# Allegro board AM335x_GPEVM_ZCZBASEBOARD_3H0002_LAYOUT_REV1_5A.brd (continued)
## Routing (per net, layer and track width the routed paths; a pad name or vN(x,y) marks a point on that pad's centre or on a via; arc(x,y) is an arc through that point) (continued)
N17345501: length 2.7
  TOP w0.121: v1(153.96,91.73) SW4.1
  BOTTOM w0.121: R122.2 v1(153.96,91.73)
N17345515: length 2.7
  TOP w0.121: v1(153.96,89.19) SW4.2
  BOTTOM w0.121: R123.2 v1(153.96,89.19)
N17345519: length 2.7
  TOP w0.121: v1(153.96,86.65) SW4.3
  BOTTOM w0.121: R124.2 v1(153.96,86.65)
N17345529: length 2.7
  TOP w0.121: v1(153.96,84.11) SW4.4
  BOTTOM w0.121: R125.2 v1(153.96,84.11)
N17345551: length 2.7
  TOP w0.121: v1(153.96,81.57) 155.61,81.57
  BOTTOM w0.121: R126.2 v1(153.96,81.57)
N17345553: length 2.7
  TOP w0.121: v1(153.96,79.03) SW4.6
  BOTTOM w0.121: R127.2 v1(153.96,79.03)
N17345567: length 2.7
  TOP w0.121: v1(153.96,76.49) SW4.7
  BOTTOM w0.121: R128.2 v1(153.96,76.49)
N17345577: length 2.7
  TOP w0.121: v1(153.96,73.95) SW4.8
  BOTTOM w0.121: R129.2 v1(153.96,73.95)
N17563948: length 133.9
  TOP w0.121: R84.1 76.72,104.66 v1(76.72,104.94) ; Q1.G 35.71,162.1 R86.2 38.06,162.09 42.91,157.24 57.24,157.24 58.05,156.42 58.05,154.85 58.53,154.37 59.9,154.37 60.46,154.93 67.93,154.93 68.67,154.19 v1(74.41,154.19) 74.81,154.59 81.56,154.59 81.82,154.33 84.55,154.33 84.79,154.09 85.21,154.09 86.02,154.9 R85.1 86.27,155.61 v1(86.78,156.12) ; v1(98.46,155.61) 98.59,155.74 R509.1
  BOTTOM w0.121: v1(98.46,155.61) 98.84,155.99 98.84,160.25 97.96,161.13 89.31,161.13 88.87,160.69 88.87,158.22 v1(86.78,156.12) ; v1(76.72,104.94) 76.72,105.93 77.53,106.74 v1(77.53,116.5) 77.53,117.44 77.14,117.82 77.14,119.18 73.74,122.58 73.74,128.68 74.97,129.91 74.97,135.61 74.67,135.91 74.67,140.39 73.95,141.11 73.95,148.5 74.08,148.63 74.08,150.79 73.95,150.91 73.95,153.73 v1(74.41,154.19)
N17563994: length 1.9
  TOP w0.121: D4.2 35.6,167.06 v1(35.6,168.03)
  BOTTOM w0.121: R80.1 v1(35.6,168.03)
N17563997: length 2.7
  TOP w0.121: Q1.D 33.33,164.88 D4.1
N17564510: length 2.8
  TOP w0.121: D5.1 29.26,166.79 Q2.D
N17564514: length 2
  TOP w0.121: D5.2 v1(31.26,168.06)
  BOTTOM w0.121: v1(31.26,168.06) 31.26,167.97 31.28,167.96 R81.1
N17564644: length 2.8
  TOP w0.121: D6.1 24.81,166.79 Q3.D
N17564648: length 2
  TOP w0.121: v1(26.83,168.06) 26.83,167.06 D6.2
  BOTTOM w0.121: R82.1 v1(26.83,168.06)
N17564780: length 2.7
  TOP w0.121: D7.1 20.37,166.92 Q4.D
N17564784: length 2
  TOP w0.121: D7.2 v1(22.5,168.06)
  BOTTOM w0.121: R83.1 22.52,167.96 22.5,167.97 v1(22.5,168.06)
N17564892: length 216.9
  TOP w0.121: 93.26,155.74 v1(92.49,155.74) 92.49,157.96 91.48,158.98 91.48,162.72 90.78,163.42 81.83,163.42 81.19,162.79 81.19,162.09 80.3,161.2 78.27,161.2 75.73,158.66 70.4,158.66 67.98,156.25 v1(58.58,156.25) ; R87.1 77.2,100.54 77.2,102.08 77.24,102.11 77.24,102.48 77.2,102.52 v1(77.2,102.91) 77.2,103.26 77.15,103.31 77.15,104.54 77.53,104.91 77.53,105.09 R88.1 ; v1(32.3,163.11) 32.3,162.22 32.04,161.96 R93.2 31.27,161.97 Q2.G ; v1(22.64,156.69) v1(53.38,156.69)
  LY3 w0.133: v1(22.64,156.69) 23.77,155.56 28.13,155.56 32.3,159.73 v1(32.3,163.11) ; v1(22.18,103.38) 23.1,104.3 52.36,104.3 53.28,103.39 66.18,103.39 67.42,104.62 68.17,104.62 69.89,102.91 72.93,102.91 73.26,102.59 74.52,102.59 74.84,102.91 v1(77.2,102.91)
  BOTTOM w0.121: v1(58.58,156.25) 58.14,156.69 v1(53.38,156.69) ; v1(22.64,156.69) 22.64,148.2 23.21,147.63 23.21,117.41 23.36,117.26 23.36,114.97 23.21,114.82 23.21,112.34 21.45,110.57 21.45,104.73 22.18,104 v1(22.18,103.38)
N17564904: length 188.3
  TOP w0.121: v1(24.04,156.12) v1(54.14,156.12) ; R511.1 87.16,153.83 85.65,153.83 85.41,153.6 84.59,153.6 84.47,153.71 68.03,153.71 67.15,154.59 66.55,154.59 65.98,154.01 58.54,154.01 57.31,155.24 v1(57.31,156.12) ; v1(27.98,162.47) 27.47,161.96 R95.2 26.83,163.42 Q3.G ; v1(23.66,102.94) 35.24,102.94 35.26,102.97 35.63,102.97 35.65,102.94 41.28,102.94 42.76,104.42 50.96,104.42 52.16,105.62 65.14,105.62 66.12,104.65 66.68,104.65 66.94,104.91 68.21,104.91 69.26,103.86 70.07,103.86 R90.1 R89.1
  LY3 w0.133: v1(24.04,156.12) 25.54,156.12 26.83,157.42 26.83,158.36 27.98,159.5 v1(27.98,162.47)
  BOTTOM w0.121: v1(57.31,156.12) v1(54.14,156.12) ; v1(23.66,102.94) 23.66,104.05 21.69,106.02 21.69,110.46 23.46,112.23 23.46,114.64 23.61,114.79 23.61,120 23.46,120.15 23.46,148.24 23.13,148.58 23.13,155.21 v1(24.04,156.12)
N17564916: length 157.6
  TOP w0.121: v1(23.25,161.96) R94.2 22.38,161.97 Q4.G ; R91.1 73.51,97.64 73.51,98.53 72.8,99.23 72.47,99.23 72.47,99.23 71.88,99.23 71.87,99.23 71.46,99.23 71.45,99.23 71.28,99.23 71.06,99.44 71.06,102.31 69.76,103.62 69.16,103.62 68.11,104.67 67.04,104.67 66.78,104.4 66.01,104.4 65.04,105.38 52.4,105.38 52.22,105.19 52.21,105.19 51.19,104.18 42.86,104.18 41.19,102.5 35.93,102.5 35.9,102.53 v1(35.44,102.53) ; v1(59.6,133.01) 58.84,133.77 57.44,133.77 56.17,135.04 55.28,135.04 54.52,135.8 47.28,135.8 v1(46.52,136.56) ; R92.1 44.6,115.61 43.78,114.79 43.53,114.79 42.75,114.01 40.82,114.01 40.14,113.34 39.45,113.34 39.19,113.6 39.19,113.63 39.15,113.67 v1(39.15,115.35) 37.5,115.35 36.64,114.49 v1(36.64,113.07)
  BOTTOM w0.121: v1(35.44,102.53) 35.44,111.87 v1(36.64,113.07) ; R512.1 v1(59.6,133.01) ; v1(39.15,115.35) 39.15,116.01 44.61,121.47 44.61,131.74 46.52,133.64 v1(46.52,136.56) 46.52,140.3 45.55,141.26 45.55,144 41.97,147.59 41.97,158.18 37.3,162.85 33.31,162.85 32.47,162.01 23.74,162.01 23.69,161.96 v1(23.25,161.96)
N17601395: length 84.6
  TOP w0.121: v1(17.87,109.54) 17.31,108.98 R492.2 ; R349.2 65.19,95.03 v1(64.91,95.31) ; U14.7 v1(21.85,126.38)
  LY3 w0.133: v1(17.87,109.54) 16.72,108.39 16.72,104.4 19.29,101.84 23.56,101.84 24.24,102.52 24.41,102.52 25.31,103.42 38.15,103.42 42.58,98.99 46.66,98.99 50.33,95.31 v1(64.91,95.31)
  BOTTOM w0.121: v1(17.87,109.54) 17.87,109.56 19.21,110.91 20.61,110.91 21.78,112.08 21.78,115.3 22.39,115.91 22.39,124.75 21.85,125.29 v1(21.85,126.38)
N17618848: length 9.8
  TOP w0.121: U25.6 29.48,55.36 29.42,55.41 26.96,55.41 26.3,56.07 26.3,56.85 24.92,58.22 Y3.1 22.12,58.22 C212.2
N17618850: length 8.9
  TOP w0.121: C204.2 22.79,53.76 23.15,54.12 Y3.2 24.92,54.12 26.09,55.28 26.74,55.28 26.86,55.16 29.29,55.16 29.5,54.96 U25.7
N17618867: length 6.7
  TOP w0.121: U25.45 32.18,58.82 32.1,58.91 32.1,59.63 32.31,59.84 32.31,63.55 TP47.1
N17619022: length 8.5
  TOP w0.121: U25.42 33.38,60.21 32.81,60.79 32.81,63.04 33.13,63.36 34.15,63.36 34.45,63.66 34.71,63.66 35.09,64.05 35.34,64.05 TP49.1
N17619024: length 7.5
  TOP w0.121: TP48.1 33.67,63.64 33.06,63.64 32.56,63.14 32.56,60.69 32.98,60.26 32.98,59.33 33.03,59.28 33.03,58.92 32.98,58.88 U25.43
N17619221: length 4.8
  TOP w0.121: U25.40 34.18,59.71 v1(34.58,60.11) R405.1 R479.1
  BOTTOM w0.121: v1(34.58,60.11) R405.1
N17619435: length 1.1
  BOTTOM w0.121: R395.2 TP50.1
N17619707: length 3
  TOP w0.121: U25.41 33.78,60.52 R394.2
N17619739: length 6.4
  TOP w0.121: U25.46 31.78,59.7 32.06,59.98 32.06,64.28 TP46.1
N17684279: length 4.4
  TOP w0.121: R239.1 v1(129.45,79.79)
  BOTTOM w0.102: 130.72,79.54 132.12,79.54 J8.12
  BOTTOM w0.121: 130.72,79.54 129.7,79.54 v1(129.45,79.79)
N17684406: length 119.6
  TOP w0.121: U4.33 88.45,37.36 88.36,37.44 v1(88.36,37.53) ; v1(13.12,17.06) R629.1 13.09,16.13 SW6.3 SW6.4
  LY3 w0.133: v1(56.93,34.33) 54.65,34.33 54.58,34.39 27.92,34.39 22.9,29.37 22.9,24.29 21.88,23.28 16.29,23.28 15.02,22.01 15.02,18.33 13.88,17.18 13.25,17.18 v1(13.12,17.06)
  LY4 w0.133: v1(88.36,37.53) 87.91,37.53 87.29,38.16 84.77,38.16 84.69,38.08 84.55,38.08 83.6,37.13 83.6,36.36 83.22,35.98 83.22,25.18 82.33,24.29 79.16,24.29 76.24,27.22 63.03,27.22 60.94,29.31 60.68,29.31 60.42,29.57 60.42,29.82 57.44,32.8 57.44,33.82 v1(56.93,34.33)
  BOTTOM w0.203: R63.1 87.79,39.2 87.62,39.03 87.62,37.98 88.07,37.53 v1(88.36,37.53)
N17710761: length 4.8
  TOP w0.102: v2(84.2,79.4) U2.J3
  BOTTOM w0.121: R22.2 83.1,76.82 83.49,77.21 83.52,77.21 83.77,77.46 83.77,78.27 83.95,78.45 83.95,78.89 84.2,79.14 v2(84.2,79.4)
N18082443: length 93.4
  TOP w0.121: U13.4 v1(28.18,118.08) ; R328.2 81.91,154.6 81.66,154.84 70.05,154.84 69.63,155.26 59.15,155.26 v1(58.74,154.84) ; v1(55.62,154.84) v1(32.84,154.84)
  BOTTOM w0.121: v1(58.74,154.84) v1(55.62,154.84) ; v1(28.18,118.08) 28.15,118.1 28.15,134.25 32.17,138.26 32.17,154.16 v1(32.84,154.84)
N18136628: length 17.2
  TOP w0.121: U7.7 139.67,71.98 v1(139.74,72.05)
  BOTTOM w0.121: TP54.1 137.2,61.89 137.2,70.14 139.1,72.05 v1(139.74,72.05) 139.74,70.9
N18365790: length 3
  TOP w0.203: v1(84.78,35.34) 85.02,35.1 85.71,35.1 85.72,35.09 U4.39
  BOTTOM w0.381: R57.1 84.65,35.47 v1(84.78,35.34)
N18368859: length 1.9
  TOP w0.203: U6.7 93.26,23.78 R69.2
N19410176: length 3.5
  TOP w0.121: U15.6 27.76,138.43 v1(28.1,138.09)
  BOTTOM w0.121: R518.1 28.36,138.34 v1(28.1,138.09)
N19410226: length 2.4
  TOP w0.121: U13.12 v1(19.02,118.73)
  BOTTOM w0.121: R519.1 18.4,118.73 v1(19.02,118.73)
N19440113: length 0.4
  TOP w0.121: U24.B2 U24.B1
N19440133: length 0.4
  TOP w0.121: U24.D2 U24.D1
N19440219: length 2.9
  TOP w0.121: U24.A3 U24.B3 U24.C4 U24.D4 155.59,144.71 C264.1
N19490589: length 9.9
  TOP w0.102: 77.1,80.08 77.2,80.08 77.21,80.07 77.93,80.07 U2.A3
  TOP w0.121: TP24.1 69.9,78.66 70.78,78.66 71.16,79.03 71.51,79.03 71.89,79.42 75.74,79.42 76.39,80.08 77.1,80.08
N19558182: length 2.1
  TOP w0.121: U32.2 59.97,35.65 R544.1
N19577113: length 3.4
  TOP w0.121: U4.26 91.25,37.21 91.41,37.38 v1(92.49,37.38)
  BOTTOM w0.121: 91.86,36.11 92.11,36.36 92.11,36.99 v1(92.49,37.38)
N19577116: length 4.7
  TOP w0.121: v1(93.38,34.45) 92.82,33.89 U4.19
  BOTTOM w0.121: v1(93.38,34.45) 92.64,35.2 92.64,36.63 93,36.99 R60.1
N21001557: length 9.1
  TOP w0.121: SW5.2 6.8,45.52 7.07,45.25 v1(7.94,45.25) 7.94,44.54 6.8,43.4 SW5.1
  BOTTOM w0.121: v1(7.94,45.25) R156.2 R112.2
N21001559: length 8
  TOP w0.635: SW5.3 10.8,43.25 v1(10.83,43.34) ; SW5.4 v1(10.8,45.45)
  BOTTOM w0.121: v1(10.83,43.34) 10.8,43.38 v1(10.8,45.45) 10.83,45.48 R559.1 R560.2
N21339295: length 1.8
  TOP w0.121: Q5.D 128.6,160.95 129.39,161.73 R23.2
N21519462: length 2.4
  TOP w0.121: v1(92.18,57.44) U33.H8
  BOTTOM w0.076: 92.7,56.36 92.59,56.47 92.59,57.03 v1(92.18,57.44)
  BOTTOM w0.121: R572.2 92.75,56.32 92.7,56.36
N21521030: length 2.4
  TOP w0.121: v1(77.58,57.44) U34.H8
  BOTTOM w0.121: R573.2 78.14,56.32 77.99,56.47 77.99,57.03 v1(77.58,57.44)
N21540235: length 3.7
  TOP w0.121: v1(11.98,74.81) 11.01,74.81 10.31,75.52 U58.14
  BOTTOM w0.121: R585.1 v1(11.98,74.81)
N21540301: length 2.2
  TOP w0.121: D11.1 15.04,87.18 R586.2
N21540351: length 3.4
  TOP w0.121: U61.4 13.75,88.55 13.63,88.43 R588.1 12.48,87.92
N21540405: length 3
  TOP w0.121: U58.60 13.27,85.17 13.5,85.39 13.5,86.14 13.63,86.27 R586.1
N21540429: length 3.2
  TOP w0.121: U58.36 23.18,76.02 23.22,75.98 TP52.1
N21815253: length 1.9
  TOP w0.121: 21.5,97.07 20.81,97.07 20.46,96.71 U54.4
N21825062: length 4.5
  TOP w0.121: U58.59 v1(13.77,82.61)
  BOTTOM w0.121: R627.2 R591.1 14.09,83.4 14.09,82.92 v1(13.77,82.61) 14.01,82.37 R590.2
N21837772: length 3.7
  TOP w0.121: R592.2 18.58,69.5 18.77,69.7 U58.32
N21889047: length 3.7
  TOP w0.121: R593.2 16.55,69.5 16.77,69.73 U58.28
N22489222: length 4.1
  TOP w0.121: v1(105.16,57.81) 107.79,57.81 R594.1
  BOTTOM w0.121: U62.9 v1(105.16,57.81)
N22502363: length 3.4
  BOTTOM w0.381: C337.1 R603.1 103.03,51.83 103.66,52.45 U62.5
N22504661: length 4.9
  BOTTOM w0.121: R597.1 C341.1 R596.2 107.34,52.42 107.3,52.39 106.36,53.33 U62.1
N22518686: length 2
  TOP w0.121: R625.1 R624.1 C352.1
N22552028: length 4.2
  TOP w0.121: U63.1 67.28,100.05 68.21,100.98 69.53,100.98 R9.1
N22597176: length 3
  TOP w0.121: U4.38 85.69,35.49 85.25,35.93 TP53.1
N23180701: length 2.2
  TOP w0.121: C7.1 61.98,102.62 62.91,102.62 63.58,101.95 U63.4

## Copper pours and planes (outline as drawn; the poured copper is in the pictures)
DGND on TOP: 155.36,146.34 154.6,146.34 154.09,145.83 154.09,143.8 153.96,143.67 153.07,143.67 152.95,143.8 152.95,144.56 152.44,144.56 151.42,145.58 147.48,145.58 147.36,145.45 147.36,142.91 147.74,142.53 156.37,142.53 156.5,142.66 156.5,146.34 156.37,146.34 156.25,146.21 156.25,145.83 155.99,145.58 155.99,144.06 155.1,144.06 155.1,145.83 155.36,146.09
DGND on LY2_GND: 1.27,1.28 39.49,1.28 39.64,1.43 39.64,2.01 39.83,2.21 40.86,2.21 41.03,2.04 41.03,1.49 41.25,1.27 168.73,1.27 168.73,168.73 1.27,168.73
DGND on LY5_GND: 1.27,1.27 168.73,1.27 168.73,168.73 1.27,168.73
V1_2D on TOP: 149.26,15.53 155.99,15.53 156.37,15.91 156.37,18.96 156.12,19.21 151.93,19.21 151.8,19.09 151.8,17.06 151.55,16.8 149.9,16.8 149.77,16.93 149.01,16.93 149.01,15.79
V1_8D on LY4: 134.78,125.64 137.96,125.64 137.96,116.62 134.28,116.62 134.28,50.08 132.24,50.08 132.24,88.3 129.83,88.3 129.83,122.34 134.53,122.34 134.53,125.39
V3_3D on TOP: 113.96,24.93 112.05,24.93 111.92,24.8 111.92,23.91 111.67,23.66 110.65,23.66 110.65,22.64 110.78,22.52 113.83,22.52 113.96,22.64
V3_3D on BOTTOM: 111.42,22.01 113.58,22.01 113.96,22.39 113.96,24.68 113.7,24.93 111.29,24.93 111.16,24.8 111.16,22.26
V3_3D on LY4: 47.28,139.1 47.28,139.23 36.87,139.23 36.87,115.1 10.07,115.1 10.07,95.16 28.36,95.16 28.36,66.59 39.53,66.59 39.53,50.58 28.74,50.58 28.74,56.93 27.09,56.93 27.09,51.35 12.1,51.35 12.1,47.79 7.3,47.79 7.3,57.01 1.43,57.01 1.43,1.31 114.72,1.31 114.72,25.82 102.27,25.82 102.27,7.66 51.22,7.66 51.22,72.33 32.93,72.33 32.93,99.35 13.63,99.35 13.63,104.3 68.24,104.3 68.24,120.31 75.6,120.31 75.6,146.85 64.43,146.85 64.43,139.1
V3_3FTDI on LY3: 1.27,71.77 1.27,80.43 8.55,80.43 8.55,98.11 20.64,98.11 20.64,71.77
V5_0D on TOP: 155.1,147.87 155.36,147.61 155.36,146.98 153.33,146.98 152.82,146.47 152.82,144.94 152.69,144.82 152.44,144.82 151.42,145.83 147.36,145.83 146.85,146.34 146.85,147.99 147.48,148.63 152.06,148.63 152.82,147.87
V5_0D on LY4: 152.95,148.63 152.95,70.01 140.37,70.01 140.37,70.14 137.96,70.14 137.96,45.25 129.32,45.25 129.32,25.56 126.53,25.56 126.53,49.57 134.66,49.57 134.66,116.37 138.21,116.37 138.21,125.89 134.53,125.89 134.15,125.51 134.15,122.97 129.7,122.97 129.7,130.34 148.5,130.34 148.5,148.63
VBAT on TOP: 159.8,146.47 159.8,149.39 159.55,149.64 158.15,149.64 157.39,148.88 157.39,148.25 156.63,147.48 156.63,146.85 157.14,146.85 157.52,146.47
VBAT on TOP: 11.21,150.91 15.02,150.91 15.15,151.04 15.15,151.68 14.9,151.93 11.21,151.93
VBAT on TOP: 83.35,10.58 93.38,10.58 93.89,11.09 93.89,14.01 91.48,16.42 91.48,18.71 91.22,18.96 91.22,21.88 87.79,21.88 87.54,21.63 86.65,21.63 86.65,21.75 86.52,21.75 86.52,22.26 82.97,22.26 82.97,18.96 86.14,18.96 86.27,18.83 86.27,14.9 85.89,14.52 78.4,14.52 78.33,14.45 77.82,14.45 77,13.63 77,8.8 77.25,8.55 78.9,8.55 79.67,9.31 79.67,11.21 80.05,11.59 82.33,11.59
VBAT on LY4: 106.21,163.74 106.21,157.9 120.43,157.9 120.43,42.46 98.34,42.46 98.34,37.88 83.86,37.88 83.86,22.9 56.68,22.9 56.68,84.11 50.71,84.11 50.71,103.8 14.01,103.8 14.01,99.61 33.44,99.61 33.44,72.63 51.6,72.63 51.6,8.04 101.89,8.04 101.89,26.33 115.1,26.33 115.1,1.28 138.44,1.28 138.44,2.96 139.1,3.62 140.63,3.62 140.63,8.93 142.28,10.58 142.28,24.04 141.39,24.93 126.4,24.93 126.4,50.08 131.86,50.08 131.86,87.29 128.82,87.29 128.82,148.88 153.33,148.88 153.33,145.96 159.3,145.96 159.3,154.47 134.53,154.47 134.53,163.74
VBUS1_OTG_CAP on TOP: 153.38,161.15 153.38,156.91 154.09,156.2 159.6,156.2 159.9,156.5 159.9,160.13 158.66,161.38 153.61,161.38
VDD1_SMPS on TOP: 79.54,43.29 80.81,43.29 81.32,43.8 81.32,46.28 79.16,46.28 79.16,43.67
VDD1_SMPS on TOP: 72.3,37.68 74.99,37.68 75.25,37.43 75.25,36.21 75.02,35.98 72.45,35.98 72.27,36.16 72.27,37.65
VDD1_SMPS on LY3: 125.2,51.22 125.2,45.5 121.7,45.5 121.7,44.11 76.11,44.11 76.11,34.07 66.71,34.07 66.71,47.28 117.39,47.28 117.39,51.22
VDD2_SMPS on TOP: 76.24,36.49 77.76,36.49 78.27,36.99 78.27,38.65 78.14,38.77 76.24,38.77 76.11,38.65 76.11,36.61
VDD2_SMPS on TOP: 68.74,49.06 69.51,49.06 69.89,48.68 70.52,48.68 70.78,48.42 70.78,47.28 70.27,46.77 69.89,46.77 69.76,46.9 69.76,47.79 69.63,47.92 68.74,47.92
VDD2_SMPS on LY4: 78.14,39.03 75.98,39.03 75.98,32.63 72.43,32.63 72.43,48.93 69.25,48.93 69.25,29.48 78.14,29.48
VDD3_SMPS on TOP: 90.97,44.74 93.13,44.74 93.26,44.87 93.26,46.52 92.87,46.9 91.1,46.9 90.84,46.65 90.84,44.87
VDD_CORE on TOP: 72.55,46.77 72.55,45.76 72.81,45.5 75.09,45.5 75.6,46.01 75.6,46.9 75.22,47.28 73.06,47.28
VDD_CORE on BOTTOM: 73.06,47.28 72.55,46.77 72.55,45.76 72.81,45.5 75.09,45.5 75.6,46.01 75.6,46.77 75.09,47.28
VDD_CORE on LY3: 85.38,83.86 86.91,83.86 87.03,83.73 87.03,75.86 86.02,74.84 77.63,74.84 77.63,70.01 77.38,69.76 64.55,69.76 64.17,70.14 64.17,77.89 64.81,78.52 75.22,78.52 77.38,80.68 82.21,80.68
VDD_CORE on LY4: 82.33,86.97 82.33,81.57 86.02,81.57 86.02,82.33 86.78,82.33 86.78,83.98 88.56,83.98 88.56,88.49 88.37,88.68 85.32,88.68 84.43,87.79 83.92,87.79 83.1,86.97
VDD_MPU on TOP: 72.25,34.96 74.56,34.96 74.92,34.61 74.92,32.98 74.61,32.68 73.87,32.68 73.29,33.26 72.3,33.26 72.17,33.39 72.17,34.89
VDD_MPU on LY3: 84.37,88.43 84.62,88.18 84.62,87.79 84.24,87.41 84.24,85.25 83.73,84.75 82.33,84.75 81.83,84.24 81.83,83.86 81.19,83.22 80.3,83.22 80.17,83.1 78.14,83.1 75.86,80.81 67.22,80.81 66.97,80.56 64.55,80.56 64.43,80.68 64.43,82.71 73.06,82.71 74.21,83.86 76.11,83.86 79.03,86.78 79.54,86.78 79.92,86.4 80.43,86.4 80.94,85.89 81.44,86.4 81.44,88.43
VDDH_PHY on TOP: 27.28,52.74 28.36,52.74 29.18,53.57 30.26,53.57 30.26,53.95 28.49,53.95 28.04,53.5 27.28,53.5
VDDH_PHY on LY3: 25.95,58.74 25.95,52.89 29.5,52.89 29.5,58.74
VDDR_VREF on BOTTOM: 103.85,56.04 103.06,56.04 102.91,56.2 102.91,59.17 102.93,59.19 103.49,59.19 103.64,59.04 103.64,58.08 103.9,57.82 103.9,56.09
VDDR_VTT on TOP: 88.18,66.71 97.75,66.71 97.75,68.24 88.18,68.24
VDDR_VTT on BOTTOM: 95.69,52.54 95.69,54.04 82.84,54.04 82.64,53.83 82.64,52.56 82.66,52.54
VDDR_VTT on LY4: 87.72,69.61 88.15,70.04 105.04,70.04 105.04,51.55 84.54,51.55 83.58,52.51 83.58,54.62 83.63,54.67 100.77,54.67 100.77,66.66 87.72,66.66
VDDS_DDR on LY3: 67.09,69.51 67.09,54.52 67.35,54.27 97.88,54.27 97.88,51.29 109.77,51.29 109.77,54.01 110.86,54.01 110.86,59.6 104.43,59.6 103.92,60.11 103.92,61 105.19,62.27 105.19,65.7 106.46,66.97 106.46,69.68 106.01,70.14 104,70.14 103.36,69.51 88.1,69.51 88.1,72.27 84.29,72.27 84.29,69.51
VDDS_RTC on LY4: 80.43,82.9 80.43,80.62 69.82,80.62 69.82,81.83 71.6,83.6 79.73,83.6
VDDSHV2 on LY3: 19.87,113.04 19.87,110.65 22.59,107.94 42.07,107.94 47.64,113.5 76.44,113.5 76.85,113.91 79.49,113.91 80.71,115.12 80.71,118.78 79.74,119.75 78.8,119.75 78.73,119.67 77.79,119.67 77.41,119.29 77.41,118.38 77.94,117.84 77.94,116.42 77.67,116.15 73.23,116.15 73.14,116.06 43.93,116.06 43.6,116.39 42.02,116.39 38.11,112.48 23.25,112.48 22.52,113.22 20.05,113.22
VDDSHV4 on LY4: 42.2,143.42 42.2,164.88 61.51,164.88 61.51,163.61 105.96,163.61 105.96,157.64 117,157.64 117,148.75 114.34,148.75 114.34,155.49 76.62,155.49 76.62,147.23 57.7,147.23 57.7,143.42
VDDSHV6 on LY4: 141.26,1.27 141.26,8.93 142.91,10.58 142.91,18.71 152.44,18.71 152.44,26.58 150.02,26.58 150.02,41.69 132.24,41.69 132.24,25.77 129.58,25.77 129.58,45 138.21,45 138.21,69.89 159.68,69.89 159.68,154.85 134.91,154.85 134.91,163.87 61.76,163.87 61.76,165.26 41.82,165.26 41.82,143.42 58.33,143.42 58.33,146.98 63.92,146.98 63.92,139.74 36.49,139.74 36.49,115.35 9.82,115.35 9.82,94.65 28.1,94.65 28.1,61.51 23.41,61.51 23.41,51.73 11.72,51.73 11.72,48.17 7.61,48.17 7.61,57.36 7.58,57.39 1.31,57.39 1.31,168.69 143.42,168.69 143.42,168.73 168.28,168.73 168.73,168.28 168.73,1.72 168.28,1.27
AM335X_VDDS on LY3: 80.56,81.95 80.56,80.91 82.18,80.91 85.38,84.11 87.29,84.11 87.29,81.63 87.41,81.51 88.62,81.51 88.68,81.57 88.68,83.79 89.38,83.79 89.38,85.13 88.81,85.13 88.56,85.38 88.56,88.43 88.68,88.56 89.57,88.56 89.83,88.3 91.48,88.3 92.49,89.32 94.14,89.32 94.14,90.46 94.02,90.59 91.99,90.59 91.86,90.52 90.84,89.51 85.7,89.51 85.57,89.64 85.57,94.14 85.59,94.16 85.59,95.09 87.39,96.89 87.39,97.4 87.77,97.78 88.23,97.78 88.65,98.2 88.65,98.75 87.92,99.48 84.03,99.48 83.1,98.54 83.1,93 81.95,93 80.68,91.73 80.68,88.94 81.06,88.56 84.37,88.56 84.75,88.18 84.75,87.67 84.37,87.29 84.37,85.13 83.86,84.62 82.46,84.62 81.95,84.11 81.95,83.6 81.83,83.48 81.83,83.35 81.44,82.97 81.44,82.33 81.25,82.14 80.75,82.14
AM335X_VDDS_DDR on BOTTOM: 81.32,80.81 83.73,80.81 83.98,80.56 86.78,80.56 86.91,80.68 86.91,81.19 86.78,81.32 83.98,81.32 83.86,81.44 83.86,81.83 83.6,82.08 81.32,82.08 81.19,81.95 81.19,80.94
AM335X_VDDS_DDR on LY4: 82.33,81.32 82.33,80.56 87.79,80.56 87.79,81.44 88.56,81.44 88.56,81.98 88.81,82.23 89.29,82.23 89.83,81.7 92.62,81.7 92.62,82.87 92.42,83.07 92.01,83.07 91.88,83.2 91.88,83.25 91.27,83.86 86.91,83.86 86.91,82.21 86.14,82.21 86.14,81.32
AM335X_VDDSHV3 on LY3: 89.45,88.43 88.75,88.43 88.62,88.3 88.62,86.52 88.87,86.27 91.73,86.27 92.37,86.91 92.87,86.91 93.51,87.54 94.14,87.54 94.27,87.67 94.27,88.94 94.14,89.06 92.49,89.06 91.48,88.05 89.83,88.05
AM335X_VDDSHV6 on LY3: 48.93,83.98 66.84,83.98 67.86,82.97 72.94,82.97 74.14,84.17 76.05,84.17 79.03,87.16 79.54,87.16 80.05,86.65 80.43,86.65 80.81,86.27 81.06,86.27 81.32,86.52 81.32,88.43 80.94,88.43 80.17,89.19 80.17,91.99 79.54,92.62 78.27,92.62 75.67,90.02 75.67,88.24 73.57,86.14 48.81,86.14 48.81,84.11
AM335X_VDDSHV6 on LY4: 88.81,82.08 89.22,82.08 89.45,81.85 89.45,81.7 89.57,81.57 92.62,81.57 92.62,79.79 93.38,79.79 93.38,79.03 91.1,79.03 91.1,77.76 91.13,77.73 91.1,77.7 91.1,76.81 80.56,76.81 80.56,89.19 83.1,89.19 83.1,87.16 82.21,87.16 82.21,80.3 87.92,80.3 87.92,81.06 88.18,81.32 88.56,81.32 88.68,81.44 88.68,81.95
HDMI_AVCC12 on TOP: 154.22,19.6 158.53,19.6 158.66,19.72 158.66,21.37 157.9,22.14 154.6,22.14 154.22,21.75
HDMI_CVCC12 on LY4: 132.63,25.69 132.63,32.93 135.8,32.93 135.8,34.45 134.66,34.45 134.66,39.53 142.4,39.53 142.4,34.96 147.61,34.96 147.61,30.52 146.34,30.52 146.34,28.49 149.64,28.49 149.64,26.07 151.93,26.07 151.93,19.21 142.91,19.21 142.91,24.04 141.26,25.69
HDMI_IOVCC on LY4: 135.55,33.18 132.63,33.18 132.63,41.31 149.64,41.31 149.64,28.87 146.6,28.87 146.6,30.26 147.87,30.26 147.87,35.22 142.66,35.22 142.66,39.79 134.4,39.79 134.4,34.2 135.55,34.2
LDO_VRTC on TOP: 82.59,25.95 83.86,25.95 83.86,23.02 83.73,22.9 82.71,22.9 82.59,22.77 81.83,22.77 81.83,24.29 82.59,25.06
PWR_SMPS3 on TOP: 89.06,38.44 89.06,36.74 89.45,36.74 89.45,38.21 89.88,38.65 89.88,39 89.62,39.25 89.39,39.25 89.22,39.08 89.22,38.59
PWR_SWIO on TOP: 94.91,29.88 96.43,29.88 96.56,30.01 96.56,35.09 95.29,35.09 94.02,33.82 94.02,32.17 93.76,31.91 93.51,31.91 93.51,31.66 94.02,31.66 94.14,31.53 94.14,30.64
PWR_VAUX33 on LY4: 87.03,28.87 87.03,27.98 87.41,27.6 94.14,27.6 94.65,28.1 94.65,28.87 94.27,29.25 90.33,29.25 89.95,28.87
PWR_VDAC on TOP: 97.7,36.74 97.7,35.22 94.02,35.22 93.64,34.84 91.99,34.84 91.99,35.34 93,35.34 94.14,36.49 94.91,36.49 95.16,36.74
PWR_VDD1_SMPS on TOP: 79.26,41.44 81.04,41.44 81.55,41.95 86.5,41.95 87.13,41.31 87.26,41.31 87.64,40.93 88.4,40.93 88.4,40.91 88.61,40.7 89.17,40.7 89.29,40.83 89.29,43.67 88.68,44.28 88.68,46.39 81.95,46.39 81.52,45.96 81.52,44 80.61,43.09 79.51,43.09 79.13,42.71 79.13,41.57
PWR_VDD2_SMPS on TOP: 76.49,35.98 77.76,35.98 79.03,37.25 80.81,37.25 80.94,37.12 80.94,31.91 80.56,31.53 79.54,31.53 77.89,33.18 76.75,33.18 76.49,33.44
PWR_VDD2_SMPS on TOP: 84.11,32.8 84.11,33.06 84.49,33.44 85.64,33.44 85.89,33.18 86.4,33.18 86.4,32.93 85.76,32.93 85.64,33.06 85.25,33.06 85,32.8
PWR_VDD3_SMPS on TOP: 89.57,36.74 89.57,38.14 90.21,38.77 90.21,38.9 90.52,39.22 91.35,39.22 91.35,44.23 91.48,44.36 93.13,44.36 93.26,44.23 93.26,39.03 93,38.77 90.84,38.77 90.46,38.39 90.21,38.39 89.83,38.01 89.83,36.74
PWR_VDDIO on TOP: 93,30.39 93,30.64 92.62,31.03 91.6,31.03 91.6,30.26 92.24,30.26 92.49,30.01 92.62,30.01
PWR_VDIG2 on TOP: 87.92,27.47 87.92,28.36 88.3,28.74 88.3,29.63 88.68,30.01 88.94,30.01 88.94,27.47
PWR_VIO_SMPS on TOP: 97.57,35.09 97.57,29.88 97.83,29.63 99.48,29.63 99.73,29.37 99.73,26.61 99.76,26.58 102.75,26.58 102.91,26.73 102.91,27.95 102.12,27.95 101.97,28.1 101.97,31.08 100.24,32.8 100.24,34.96 100.11,35.09
PWR_VIO_SMPS on BOTTOM: 93.13,32.8 96.18,32.8 96.56,32.42 100.88,32.42 101.26,32.04 101.26,30.9 100.75,30.39 95.54,30.39 94.02,31.91 93.13,31.91
PWR_VMMC on TOP: 86.02,28.1 86.27,28.1 86.52,28.36 86.52,29.5 87.41,30.39 87.41,30.96 87.48,31.03 87.79,31.03 87.79,29.88 87.67,29.76 87.41,29.76 87.29,29.63 87.29,27.47 87.16,27.34 86.02,27.34
PWR_VPLL on TOP: 93.26,36.87 92.49,36.87 92.24,36.61 92.24,35.85 92.75,35.85 92.75,36.36 93,36.61 93.26,36.61
USB5V_FB on TOP: 155.36,146.85 153.45,146.85 153.07,146.47 153.07,144.06 153.33,143.8 153.83,143.8 153.96,143.93 153.96,145.83 154.6,146.47 155.36,146.47
VADDL_PHY on TOP: 27.24,64.71 29.04,64.71 29.32,64.98 29.32,66.36 29.15,66.53 27.49,66.53 27.09,66.13 27.09,64.86
VADDL_PHY on LY4: 28.99,50.96 39.15,50.96 39.15,66.33 28.49,66.33 28.49,63.54 37.5,63.54 37.63,63.41 37.63,54.14 37.38,53.89 35.72,53.89 35.47,54.14 35.47,59.47 29.37,59.47 29.37,56.81 28.99,56.81
VAUX33 on BOTTOM: 105.5,57.16 105.5,56.07 105.52,56.04 106.11,56.04 106.49,55.66 107.61,55.66 107.61,56.68 106.31,56.68 105.83,57.16
VBCKUPBAT on TOP: 92.75,38.39 92.24,38.39 91.73,37.88 91.1,37.88 90.72,37.5 90.72,36.61 90.97,36.61 90.97,37.25 91.35,37.63 92.37,37.63 92.75,38.01
VETH_LX on TOP: 27.98,57.95 27.98,56.68 28.05,56.6 29.17,56.6 29.35,56.43 30.26,56.43 30.26,56.68 29.76,56.68 29.32,57.11 29.12,57.11 28.87,57.36 28.87,57.76 29.12,58.01 29.12,59.22 28.87,59.47 28.36,59.47 27.34,60.49 27.34,62.27 27.09,62.52 26.2,62.52 26.2,60.36 26.45,60.11 26.45,59.47
VETH_VDDIO on LY4: 25.18,51.73 26.83,51.73 26.83,57.06 28.87,57.06 29.12,57.31 29.12,59.73 35.72,59.73 35.72,54.14 37.38,54.14 37.38,63.28 28.49,63.28 28.49,61.25 25.18,61.25
VPWRIN_FUSED on TOP: 65.95,8.8 75.73,8.8 76.49,9.56 76.49,13.88 74.59,15.79 74.59,22.39 64.05,22.39 63.54,21.88 63.54,11.21
VPWRIN_JCK on TOP: 51.6,12.36 56.81,12.36 58.97,14.52 58.97,20.99 58.2,21.75 51.98,21.75 50.96,20.74 50.96,13.5 51.6,12.86
VPWRIN_PREFUSE on TOP: 52.11,23.41 69.25,23.41 70.01,24.17 70.01,28.49 69.38,29.12 52.36,29.12 51.47,28.23 51.47,24.04
VRTC on TOP: 92.49,24.17 90.08,24.17 89.57,23.66 85.51,23.66 85.51,24.42 84.62,24.42 84.62,25.82 84.75,25.95 85.89,25.95 86.78,25.06 91.99,25.06 92.49,24.55
VRTC on LY3: 82.71,23.41 97.83,23.41 97.83,42.46 82.71,42.46 82.71,31.15 91.48,31.15 91.48,25.82 82.71,25.82
VUSB_VBUS0 on TOP: 132.75,148.82 136.69,148.82 136.69,152.63 135.67,153.64 132.5,153.64 132.5,149.07
VUSB_VBUS0 on TOP: 131.74,166.51 131.74,164.98 131.61,164.86 131.61,162.44 132.12,162.44 132.12,163.46 132.88,164.22 134.15,164.22 134.15,165.11 132.63,165.11 132.37,165.37 132.37,166.51
VUSB_VBUS0 on BOTTOM: 135.17,167.8 127.04,167.8 126.66,167.42 126.66,164.25 127.29,163.61 130.34,163.61 130.47,163.49 130.47,161.71 131.48,160.69 132.82,160.69 132.82,151.61 133.32,151.1 137.01,151.1 138.15,152.25 138.15,164.82
VUSB_VBUS1 on TOP: 147.17,162.53 147.17,161.58 147.67,161.58 147.67,162.6 148.44,163.36 149.95,163.36 150.48,162.83 150.48,156.73 150.99,156.22 153,156.22 153,164.3 151.01,166.28 148.12,166.28 147.99,166.15 147.99,164.25 147.87,164.12 147.23,164.12 146.98,163.87 146.98,162.72
VUSB_VBUS1 on TOP: 140.82,148.37 145.07,148.37 145.07,152.82 144.94,152.95 141.01,152.95 140.75,152.69 140.75,148.44
VUSB_VBUS1 on BOTTOM: 141.01,148.44 145.07,148.44 145.07,151.68 149.01,155.61 153.07,155.61 153.64,156.18 153.64,165.07 151.04,167.68 141.71,167.68 140.88,166.85 140.88,148.56
N19440113 on TOP: 160.31,153.07 156.5,153.07 156.5,148.12 156.12,147.74 156.12,146.98 156.25,146.85 156.37,146.85 156.5,146.98 156.5,147.48 157.26,148.25 157.26,149.01 158.28,150.02 160.31,150.02
N19440133 on TOP: 155.23,152.95 151.17,152.95 151.17,149.9 153.07,147.99 155.1,147.99 155.49,147.61 155.49,146.98 155.74,146.98 155.74,147.87 155.23,148.37

Small or netless copper shapes (teardrops, artwork), in the pictures only: 4 on TOP

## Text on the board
BOTTOM: LAYER6 - SECONDARY SIDE | 6 | PN 3H0002
Ref Des/Silkscreen Bottom: 1
User.Comments: sdf | Green indicates power/gnd routing
TOP: LAYER1 - PRIMARY SIDE | 1 | 6
Ref Des/Assembly Top: 0.1UFCAPACITOR50V10%0402_SM-735
Ref Des/Silkscreen Top: E4 | A4 | 1 | VBAT | GND | RESET | INT | VDDS_SRAM_CORE | VDDS_SRAM_MPU_BB | VDDA_ADC | VDDSHV6 | 2.5A | 5VDC | VDDS_RTC | VDDS_PLL_DDR | VDD CORE | ON | POWER | OFF | VDDSHV5V | VDDA3P3V_USB0 | VDDS | 3.0V 800uA | RS-232 0 | VDDSHV2 | VDDA1P8V_USB0 | USB0 | VDDSHV3 | HDMI | USB1 | COM | 125VAC,125VDC | 4A SLOW BLOW | SD/MMC0 Card | VDDS_PLL_MPU | AM335X_VDDS_DDR | VDDS_PLL_CORE_LCD | VDDS_OSC | VDDS_DDR | VDDSHV1 | VDDSHV4 | SYSBOOT 0-7 | SYSBOOT 8-15 | ARM MPU | AM335x ZCZ Base Board | REV 1.5A | SN#:_________________ | UL 94V0 | ASSY PN 4P0016
LY3: LAYER 3 - SINGAL 1 | 3 | 6
LY4: LAYER 4 - SIGNAL 2 | 4 | 6
PAGE_OUTLINE: LAYOUT BY | REVIEWED BY | APPROVED BY | UNLESS OTHERWISE SPECIFIED | DIMENSIONS ARE IN INCHES | TOLERANCES ON; | 2 PL DECIMALS + | 3 PL DECIMALS + | ANGLES + | FRACTIONS + | SIGNATURES | DATE | SCALE | SIZE | 1:1 | SHEET 1 OF 1 | 1.5A | REV | AM335x EVM GENERAL PURPOSE ZCZ BASE BOARD 1.5A | DESCRIPTION | REVISIONS | FABRICATION DRAWING | 08/22/2012 | APPROVED | TEXAS INSTRUMENTS | D | C | B | A | 4 | 3 | 2
DIMENSION: FAB DRAWING | 1 | 9. PLATED THROUGH SLOT INDICATED WITH MULTIPLE DRILL HITS SHOULD BE | 11. DESIGN HAS INTENTIONAL SHORTS AT SENSE RESISTORS AS SHOWN IN IPC356 NETLIST. | 10. ALL VIAS TO HAVE SOLDERMASK. | PROCESS NOTES: | 2. APPLY LPI SOLDERMASK OVER BARE COPPER (SMOBC), | COLOR: GREEN. SOLDERMASK SHALL | CONFORM TO IPC-SM-840, CLASS H. CURRENT REV. | 3. SOLDERMASK ARTWORK HAS ZERO (0) OVERSIZED PADS. | FABRICATION VENDOR IS ALLOWED TO ADJUST THE COMPONENT | SOLDERMASK PADS TO MEET THEIR TOOLING REQUIREMENTS. | 4. APPLY LPI SILKSCREEN OR EQUIVALENT PER THE ARTWORK. | COLOR: WHITE. | 1. PLATE ALL EXPOSED AREAS WITH ELECTROLESS | IMMERSION GOLD, NICKEL 150 MICROINCHES THK MIN | GOLD 5-15 MICROINCHES THK MIN. | FAB NOTES: | 1. ALL DIMENSIONS ARE IN INCHES, UNLESS | OTHERWISE NOTED. | 2. THE PWB SHALL BE FABRICATED TO IPC-6012, | CLASS 2 AND WORKMANSHIP SHALL CONFORM TO | IPC-A-600, CLASS 2. CURRENT REVISIONS. | 3. BOARD MATERIAL SHALL BE 180 Tg/350 Td ISOLA FR-370HR | OR EQUIVALENT, RoHS COMPLIANT AND LEAD FREE | ASSEMBLY CAPABLE.  BOARD MATERIAL SHALL | MEET OR EXCEED IPC-4101B. COLOR: NATURAL. | 4. BOARD MATERIAL & CONSTRUCTION TO BE U.L. | APPROVED AND MARKED ON THE FINISHED BOARD. | 5. MINIMUM COPPER WALL THICKNESS OF PLATED-THRU | HOLES TO BE .001 INCH, WITH A MINIMUM | ANNULAR RING OF .002 INCH. | 6. OVERALL BOARD THICKNESS TO BE .062 +/- 10% | AND APPLIES AFTER ALL LAMINATION AND PLATING | PROCESSES, MEASURED FROM COPPER TO COPPER. | 7. MAX. WARP & TWIST TO BE .0075 INCHES PER INCH. | 8. BOARD MUST BE ELECTRICALLY TESTED USING | SUPPLIED IPC-D-356 NETLIST. | FINISHED AS SMOOTH WALL BY VEDOR. | (OZ) | LAYER 1 - PRIMARY SIDE - SIGNAL | LAYER 2 - GROUND PLANE | LAYER 3 - SIGNAL | LAYER 4 - SIGNAL | LAYER 5 - GROUND PLANE | LAYER 6 - SECONDARY SIDE - SIGNAL | LAYER# | COPPER WEIGHT | HALF+PLATING | IMPEDANCE CONTROL | +/- 10% | 50ohm SINGLE ENDED | TRACE WIDTH | 5.25 | 4.75 | TRACE WIDTH / SPACE | 90ohm DIFFERENTIAL | 4.5/6.5 | 5.0/7.0 | 100ohm DIFFERENTIAL | 3.75/7.25 | 4.00/8.00 | LAYER STACK-UP - MILS
DEVICE_TYPE_TOP: J6 | J4 | J3 | J1
USER_PART_NUM_TOP: LAYER 2 - GND PLANE1 | 2 | 6
User.9: LAYER 5-GND PLANE2 | 5 | 6
User.10: LAYER 6 - SIGNAL 2 | 6
User.11: LAYER 7 - GND PLANE 2 | 7 | 6
User.13: SOLDERMASK TOP | 1 | 2
User.14: SOLDERMASK BOTTOM | 2
User.15: PASTEMASK TOP | 1 | 2
User.16: PASTEMASK BOTTOM | 2
User.17: SILKSCREEN TOP | 1 | 2
User.18: SILKSCREEN BOTTOM | 2
User.19: 2 | OF | SH | ASSEMBLY BOTTOM | TI-6027-01 | PRJ# | DESCRIPTION | 08-22-12 | DATE | TEXAS INSTRUMENTS | REV | 1.5A | 3H0002 | CUSTOMER NAME  : | BOARD NO : | BOARD NAME | AM335x ZCZ BASEBOARD
User.20: ASSEMBLY TOP | 1 | 2
User.21: 3H0002 | TEXAS INSTRUMENTS | 1.5A | 08-22-12 | TI-6027-01 | AM335x ZCZ BASEBOARD
User.25: FIGURE | SIZE | 8.0 | 10.0 | 18.0 | 26.0 | 35.0 | 36.0 | 40.0 | 43.0 | 50.0 | 62.0 | 63.0 | 91.0 | 120.0 | 125.0 | 140.0 | 33.0 | 61.0 | 70.0 | 110.0 | 250.0 | DRILL CHART: TOP to BOTTOM | ALL UNITS ARE IN MILS | TOLERANCE | +3.0/-3.0 | PLATED | NON-PLATED | QTY | 186 | 2725 | 18 | 60 | 10 | 4 | 229 | 9 | 6 | 2 | 1
